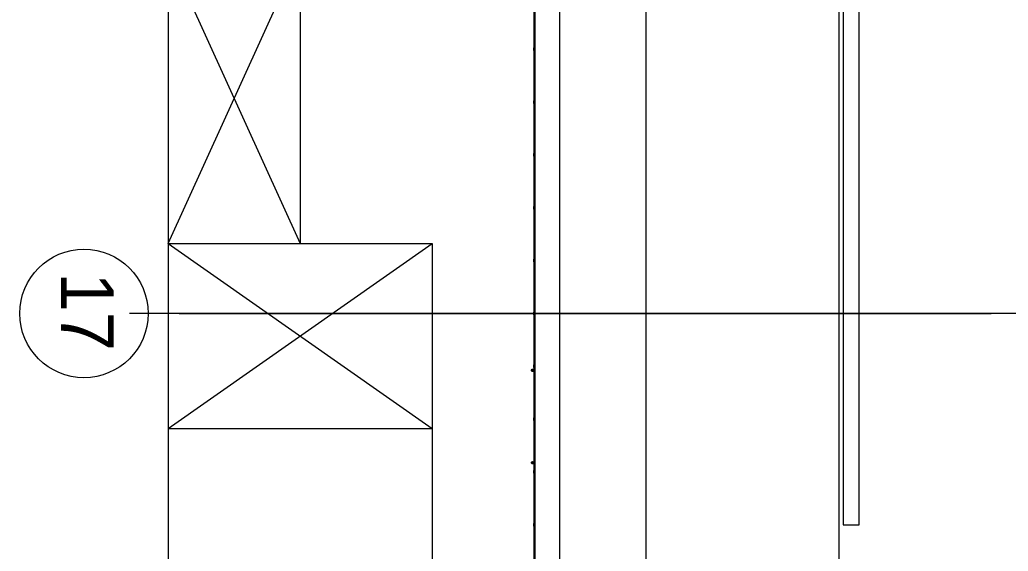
# Model space of a CAD drawing. Extents: x -264165 to -263575, y -1242333 to -1242036.
# Drawn here: x -263923.9 to -263905.18, y -1242193.38 to -1242183.32 of the extents above; entities that cross this region are included whole.
import ezdxf

# ---------------------------------------------------------------- set-up
doc = ezdxf.new("R2010")
doc.units = 0
doc.layers.add('KFA_HESCON_OSI_STAVBY', color=7, linetype='Continuous')
doc.layers.add('KFA_SITUACIA_DRS_VYTYCOVAK_SEDA', color=7, linetype='Continuous')

msp = doc.modelspace()

# ---------------------------------------------------------------- linework, layer by layer
at = {"layer": 'KFA_HESCON_OSI_STAVBY'}
for p, q in [((-263908.393, -1242080.447), (-263908.393, -1242248.737)), ((-263787.486, -1242188.882), (-263921.823, -1242188.882)), ((-263920.885, -1242188.882), (-263905.505, -1242188.882))]:
    msp.add_line(p, q, dxfattribs=at)
msp.add_circle((-263922.688, -1242188.882), 1.216, dxfattribs=at)
at = {"layer": 'KFA_SITUACIA_DRS_VYTYCOVAK_SEDA'}
for p, q in [((-263921.093, -1242087.308), (-263921.093, -1242241.458)), ((-263912.043, -1242228.625), (-263912.043, -1242100.14)), ((-263914.153, -1242132.422), (-263914.153, -1242196.342)), ((-263914.153, -1242132.422), (-263914.153, -1242196.342)), ((-263914.143, -1242196.333), (-263914.143, -1242132.433)), ((-263913.683, -1242132.892), (-263913.683, -1242195.872)), ((-263913.683, -1242132.892), (-263913.683, -1242195.872)), ((-263908.308, -1242135.882), (-263908.308, -1242192.882)), ((-263908.308, -1242135.882), (-263908.308, -1242192.882)), ((-263908.008, -1242192.882), (-263908.008, -1242135.882)), ((-263908.008, -1242192.882), (-263908.008, -1242135.882)), ((-263918.593, -1242141.207), (-263918.593, -1242187.557)), ((-263921.093, -1242182.062), (-263918.593, -1242187.557)), ((-263921.093, -1242187.557), (-263918.593, -1242182.062)), ((-263914.168, -1242182.907), (-263914.168, -1242183.857)), ((-263914.168, -1242182.907), (-263914.168, -1242183.857)), ((-263914.168, -1242183.907), (-263914.168, -1242183.857)), ((-263914.168, -1242183.907), (-263914.168, -1242183.857)), ((-263914.168, -1242183.907), (-263914.168, -1242184.857)), ((-263914.168, -1242183.907), (-263914.168, -1242184.857)), ((-263914.168, -1242184.907), (-263914.168, -1242184.857)), ((-263914.168, -1242184.907), (-263914.168, -1242184.857)), ((-263914.168, -1242184.907), (-263914.168, -1242185.857)), ((-263914.168, -1242184.907), (-263914.168, -1242185.857)), ((-263914.168, -1242185.907), (-263914.168, -1242185.857)), ((-263914.168, -1242185.907), (-263914.168, -1242185.857)), ((-263914.168, -1242185.907), (-263914.168, -1242186.857)), ((-263914.168, -1242185.907), (-263914.168, -1242186.857)), ((-263914.168, -1242186.907), (-263914.168, -1242186.857)), ((-263914.168, -1242186.907), (-263914.168, -1242186.857)), ((-263914.168, -1242186.907), (-263914.168, -1242187.857)), ((-263914.168, -1242186.907), (-263914.168, -1242187.857)), ((-263921.093, -1242187.557), (-263916.093, -1242187.557)), ((-263921.093, -1242187.557), (-263916.093, -1242191.057)), ((-263921.093, -1242191.057), (-263916.093, -1242187.557)), ((-263916.093, -1242187.557), (-263916.093, -1242241.458)), ((-263914.168, -1242187.907), (-263914.168, -1242187.857)), ((-263914.168, -1242187.907), (-263914.168, -1242187.857)), ((-263914.168, -1242187.907), (-263914.168, -1242188.857)), ((-263914.168, -1242187.907), (-263914.168, -1242188.857)), ((-263914.168, -1242188.907), (-263914.168, -1242188.857)), ((-263914.168, -1242188.907), (-263914.168, -1242188.857)), ((-263914.168, -1242188.907), (-263914.168, -1242189.857)), ((-263914.168, -1242188.907), (-263914.168, -1242189.857)), ((-263914.213, -1242189.957), (-263914.21, -1242189.947)), ((-263914.213, -1242189.957), (-263914.21, -1242189.947)), ((-263914.21, -1242189.967), (-263914.213, -1242189.957)), ((-263914.21, -1242189.967), (-263914.213, -1242189.957)), ((-263914.21, -1242189.947), (-263914.203, -1242189.939)), ((-263914.21, -1242189.947), (-263914.203, -1242189.939)), ((-263914.21, -1242189.948), (-263914.21, -1242189.947)), ((-263914.21, -1242189.948), (-263914.21, -1242189.947)), ((-263914.21, -1242189.952), (-263914.21, -1242189.948)), ((-263914.21, -1242189.952), (-263914.21, -1242189.948)), ((-263914.21, -1242189.957), (-263914.21, -1242189.952)), ((-263914.21, -1242189.957), (-263914.21, -1242189.952)), ((-263914.21, -1242189.962), (-263914.21, -1242189.957)), ((-263914.21, -1242189.962), (-263914.21, -1242189.957)), ((-263914.21, -1242189.965), (-263914.21, -1242189.962)), ((-263914.21, -1242189.965), (-263914.21, -1242189.962)), ((-263914.21, -1242189.967), (-263914.21, -1242189.965)), ((-263914.21, -1242189.967), (-263914.21, -1242189.965)), ((-263914.203, -1242189.974), (-263914.21, -1242189.967)), ((-263914.203, -1242189.974), (-263914.21, -1242189.967)), ((-263914.203, -1242189.939), (-263914.193, -1242189.937)), ((-263914.203, -1242189.939), (-263914.193, -1242189.937)), ((-263914.203, -1242189.942), (-263914.203, -1242189.939)), ((-263914.203, -1242189.942), (-263914.203, -1242189.939)), ((-263914.203, -1242189.942), (-263914.193, -1242189.939)), ((-263914.203, -1242189.942), (-263914.193, -1242189.939)), ((-263914.203, -1242189.948), (-263914.203, -1242189.942)), ((-263914.203, -1242189.948), (-263914.203, -1242189.942)), ((-263914.203, -1242189.948), (-263914.193, -1242189.947)), ((-263914.203, -1242189.948), (-263914.193, -1242189.947)), ((-263914.203, -1242189.957), (-263914.203, -1242189.948)), ((-263914.203, -1242189.957), (-263914.203, -1242189.948)), ((-263914.203, -1242189.965), (-263914.203, -1242189.957)), ((-263914.203, -1242189.965), (-263914.203, -1242189.957)), ((-263914.203, -1242189.957), (-263914.193, -1242189.957)), ((-263914.203, -1242189.957), (-263914.193, -1242189.957)), ((-263914.203, -1242189.965), (-263914.193, -1242189.967)), ((-263914.203, -1242189.965), (-263914.193, -1242189.967)), ((-263914.203, -1242189.972), (-263914.203, -1242189.965)), ((-263914.203, -1242189.972), (-263914.203, -1242189.965)), ((-263914.203, -1242189.974), (-263914.203, -1242189.972)), ((-263914.203, -1242189.974), (-263914.203, -1242189.972)), ((-263914.203, -1242189.972), (-263914.193, -1242189.974)), ((-263914.203, -1242189.972), (-263914.193, -1242189.974)), ((-263914.193, -1242189.977), (-263914.203, -1242189.974)), ((-263914.193, -1242189.977), (-263914.203, -1242189.974)), ((-263914.193, -1242189.937), (-263914.183, -1242189.939)), ((-263914.193, -1242189.937), (-263914.183, -1242189.939)), ((-263914.193, -1242189.937), (-263914.193, -1242189.939)), ((-263914.193, -1242189.937), (-263914.193, -1242189.939)), ((-263914.193, -1242189.939), (-263914.183, -1242189.942)), ((-263914.193, -1242189.939), (-263914.183, -1242189.942)), ((-263914.193, -1242189.939), (-263914.193, -1242189.947)), ((-263914.193, -1242189.939), (-263914.193, -1242189.947)), ((-263914.193, -1242189.947), (-263914.193, -1242189.957)), ((-263914.193, -1242189.947), (-263914.193, -1242189.957)), ((-263914.193, -1242189.947), (-263914.183, -1242189.948)), ((-263914.193, -1242189.947), (-263914.183, -1242189.948)), ((-263914.193, -1242189.957), (-263914.193, -1242189.967)), ((-263914.193, -1242189.957), (-263914.193, -1242189.967)), ((-263914.193, -1242189.957), (-263914.183, -1242189.957)), ((-263914.193, -1242189.957), (-263914.183, -1242189.957)), ((-263914.193, -1242189.967), (-263914.183, -1242189.965)), ((-263914.193, -1242189.967), (-263914.183, -1242189.965)), ((-263914.193, -1242189.967), (-263914.193, -1242189.974)), ((-263914.193, -1242189.967), (-263914.193, -1242189.974)), ((-263914.193, -1242189.974), (-263914.183, -1242189.972)), ((-263914.193, -1242189.974), (-263914.183, -1242189.972)), ((-263914.193, -1242189.974), (-263914.193, -1242189.977)), ((-263914.193, -1242189.974), (-263914.193, -1242189.977)), ((-263914.183, -1242189.974), (-263914.193, -1242189.977)), ((-263914.183, -1242189.974), (-263914.193, -1242189.977)), ((-263914.183, -1242189.939), (-263914.176, -1242189.947)), ((-263914.183, -1242189.939), (-263914.176, -1242189.947)), ((-263914.183, -1242189.939), (-263914.183, -1242189.942)), ((-263914.183, -1242189.939), (-263914.183, -1242189.942)), ((-263914.183, -1242189.942), (-263914.183, -1242189.948)), ((-263914.183, -1242189.942), (-263914.183, -1242189.948)), ((-263914.183, -1242189.948), (-263914.183, -1242189.957)), ((-263914.183, -1242189.948), (-263914.183, -1242189.957)), ((-263914.183, -1242189.957), (-263914.183, -1242189.965)), ((-263914.183, -1242189.957), (-263914.183, -1242189.965)), ((-263914.183, -1242189.965), (-263914.183, -1242189.972)), ((-263914.183, -1242189.965), (-263914.183, -1242189.972)), ((-263914.176, -1242189.967), (-263914.183, -1242189.974)), ((-263914.176, -1242189.967), (-263914.183, -1242189.974)), ((-263914.183, -1242189.972), (-263914.183, -1242189.974)), ((-263914.183, -1242189.972), (-263914.183, -1242189.974)), ((-263914.176, -1242189.947), (-263914.168, -1242189.947)), ((-263914.176, -1242189.947), (-263914.168, -1242189.947)), ((-263914.176, -1242189.947), (-263914.176, -1242189.948)), ((-263914.176, -1242189.947), (-263914.176, -1242189.948)), ((-263914.176, -1242189.948), (-263914.168, -1242189.948)), ((-263914.176, -1242189.948), (-263914.168, -1242189.948)), ((-263914.176, -1242189.948), (-263914.176, -1242189.952)), ((-263914.176, -1242189.948), (-263914.176, -1242189.952)), ((-263914.176, -1242189.952), (-263914.168, -1242189.952)), ((-263914.176, -1242189.952), (-263914.168, -1242189.952)), ((-263914.176, -1242189.952), (-263914.176, -1242189.957)), ((-263914.176, -1242189.952), (-263914.176, -1242189.957)), ((-263914.176, -1242189.957), (-263914.168, -1242189.957)), ((-263914.176, -1242189.957), (-263914.168, -1242189.957)), ((-263914.176, -1242189.957), (-263914.176, -1242189.962)), ((-263914.176, -1242189.957), (-263914.176, -1242189.962)), ((-263914.176, -1242189.962), (-263914.168, -1242189.962)), ((-263914.176, -1242189.962), (-263914.168, -1242189.962)), ((-263914.176, -1242189.962), (-263914.176, -1242189.965)), ((-263914.176, -1242189.962), (-263914.176, -1242189.965)), ((-263914.176, -1242189.965), (-263914.168, -1242189.965)), ((-263914.176, -1242189.965), (-263914.168, -1242189.965)), ((-263914.176, -1242189.965), (-263914.176, -1242189.967)), ((-263914.176, -1242189.965), (-263914.176, -1242189.967)), ((-263914.176, -1242189.967), (-263914.168, -1242189.967)), ((-263914.176, -1242189.967), (-263914.168, -1242189.967)), ((-263914.168, -1242189.907), (-263914.168, -1242189.857)), ((-263914.168, -1242189.907), (-263914.168, -1242189.857)), ((-263914.168, -1242189.907), (-263914.168, -1242190.857)), ((-263914.168, -1242189.907), (-263914.168, -1242190.857)), ((-263914.168, -1242190.907), (-263914.168, -1242190.857)), ((-263914.168, -1242190.907), (-263914.168, -1242190.857)), ((-263914.168, -1242190.907), (-263914.168, -1242191.857)), ((-263914.168, -1242190.907), (-263914.168, -1242191.857)), ((-263921.093, -1242191.057), (-263916.093, -1242191.057)), ((-263914.213, -1242191.707), (-263914.21, -1242191.697)), ((-263914.213, -1242191.707), (-263914.21, -1242191.697)), ((-263914.21, -1242191.717), (-263914.213, -1242191.707)), ((-263914.21, -1242191.717), (-263914.213, -1242191.707)), ((-263914.21, -1242191.697), (-263914.203, -1242191.689)), ((-263914.21, -1242191.697), (-263914.203, -1242191.689)), ((-263914.21, -1242191.698), (-263914.21, -1242191.697)), ((-263914.21, -1242191.698), (-263914.21, -1242191.697)), ((-263914.21, -1242191.702), (-263914.21, -1242191.698)), ((-263914.21, -1242191.702), (-263914.21, -1242191.698)), ((-263914.21, -1242191.707), (-263914.21, -1242191.702)), ((-263914.21, -1242191.707), (-263914.21, -1242191.702)), ((-263914.21, -1242191.712), (-263914.21, -1242191.707)), ((-263914.21, -1242191.712), (-263914.21, -1242191.707)), ((-263914.21, -1242191.715), (-263914.21, -1242191.712)), ((-263914.21, -1242191.715), (-263914.21, -1242191.712)), ((-263914.21, -1242191.717), (-263914.21, -1242191.715)), ((-263914.21, -1242191.717), (-263914.21, -1242191.715)), ((-263914.203, -1242191.724), (-263914.21, -1242191.717)), ((-263914.203, -1242191.724), (-263914.21, -1242191.717)), ((-263914.203, -1242191.689), (-263914.193, -1242191.687)), ((-263914.203, -1242191.689), (-263914.193, -1242191.687)), ((-263914.203, -1242191.692), (-263914.203, -1242191.689)), ((-263914.203, -1242191.692), (-263914.203, -1242191.689)), ((-263914.203, -1242191.692), (-263914.193, -1242191.689)), ((-263914.203, -1242191.692), (-263914.193, -1242191.689)), ((-263914.203, -1242191.698), (-263914.203, -1242191.692)), ((-263914.203, -1242191.698), (-263914.203, -1242191.692)), ((-263914.203, -1242191.698), (-263914.193, -1242191.697)), ((-263914.203, -1242191.698), (-263914.193, -1242191.697)), ((-263914.203, -1242191.707), (-263914.203, -1242191.698)), ((-263914.203, -1242191.707), (-263914.203, -1242191.698)), ((-263914.203, -1242191.715), (-263914.203, -1242191.707)), ((-263914.203, -1242191.715), (-263914.203, -1242191.707)), ((-263914.203, -1242191.707), (-263914.193, -1242191.707)), ((-263914.203, -1242191.707), (-263914.193, -1242191.707)), ((-263914.203, -1242191.715), (-263914.193, -1242191.717)), ((-263914.203, -1242191.715), (-263914.193, -1242191.717)), ((-263914.203, -1242191.722), (-263914.203, -1242191.715)), ((-263914.203, -1242191.722), (-263914.203, -1242191.715)), ((-263914.203, -1242191.724), (-263914.203, -1242191.722)), ((-263914.203, -1242191.724), (-263914.203, -1242191.722)), ((-263914.203, -1242191.722), (-263914.193, -1242191.724)), ((-263914.203, -1242191.722), (-263914.193, -1242191.724)), ((-263914.193, -1242191.727), (-263914.203, -1242191.724)), ((-263914.193, -1242191.727), (-263914.203, -1242191.724)), ((-263914.193, -1242191.687), (-263914.183, -1242191.689)), ((-263914.193, -1242191.687), (-263914.183, -1242191.689)), ((-263914.193, -1242191.687), (-263914.193, -1242191.689)), ((-263914.193, -1242191.687), (-263914.193, -1242191.689)), ((-263914.193, -1242191.689), (-263914.183, -1242191.692)), ((-263914.193, -1242191.689), (-263914.183, -1242191.692)), ((-263914.193, -1242191.689), (-263914.193, -1242191.697)), ((-263914.193, -1242191.689), (-263914.193, -1242191.697)), ((-263914.193, -1242191.697), (-263914.193, -1242191.707)), ((-263914.193, -1242191.697), (-263914.193, -1242191.707)), ((-263914.193, -1242191.697), (-263914.183, -1242191.698)), ((-263914.193, -1242191.697), (-263914.183, -1242191.698)), ((-263914.193, -1242191.707), (-263914.193, -1242191.717)), ((-263914.193, -1242191.707), (-263914.193, -1242191.717)), ((-263914.193, -1242191.707), (-263914.183, -1242191.707)), ((-263914.193, -1242191.707), (-263914.183, -1242191.707)), ((-263914.193, -1242191.717), (-263914.183, -1242191.715)), ((-263914.193, -1242191.717), (-263914.183, -1242191.715)), ((-263914.193, -1242191.717), (-263914.193, -1242191.724)), ((-263914.193, -1242191.717), (-263914.193, -1242191.724)), ((-263914.193, -1242191.724), (-263914.183, -1242191.722)), ((-263914.193, -1242191.724), (-263914.183, -1242191.722)), ((-263914.193, -1242191.724), (-263914.193, -1242191.727)), ((-263914.193, -1242191.724), (-263914.193, -1242191.727)), ((-263914.183, -1242191.724), (-263914.193, -1242191.727)), ((-263914.183, -1242191.724), (-263914.193, -1242191.727)), ((-263914.183, -1242191.689), (-263914.176, -1242191.697)), ((-263914.183, -1242191.689), (-263914.176, -1242191.697)), ((-263914.183, -1242191.689), (-263914.183, -1242191.692)), ((-263914.183, -1242191.689), (-263914.183, -1242191.692)), ((-263914.183, -1242191.692), (-263914.183, -1242191.698)), ((-263914.183, -1242191.692), (-263914.183, -1242191.698)), ((-263914.183, -1242191.698), (-263914.183, -1242191.707)), ((-263914.183, -1242191.698), (-263914.183, -1242191.707)), ((-263914.183, -1242191.707), (-263914.183, -1242191.715)), ((-263914.183, -1242191.707), (-263914.183, -1242191.715)), ((-263914.183, -1242191.715), (-263914.183, -1242191.722)), ((-263914.183, -1242191.715), (-263914.183, -1242191.722)), ((-263914.176, -1242191.717), (-263914.183, -1242191.724)), ((-263914.176, -1242191.717), (-263914.183, -1242191.724)), ((-263914.183, -1242191.722), (-263914.183, -1242191.724)), ((-263914.183, -1242191.722), (-263914.183, -1242191.724)), ((-263914.176, -1242191.697), (-263914.168, -1242191.697)), ((-263914.176, -1242191.697), (-263914.168, -1242191.697)), ((-263914.176, -1242191.697), (-263914.176, -1242191.698)), ((-263914.176, -1242191.697), (-263914.176, -1242191.698)), ((-263914.176, -1242191.698), (-263914.168, -1242191.698)), ((-263914.176, -1242191.698), (-263914.168, -1242191.698)), ((-263914.176, -1242191.698), (-263914.176, -1242191.702)), ((-263914.176, -1242191.698), (-263914.176, -1242191.702)), ((-263914.176, -1242191.702), (-263914.168, -1242191.702)), ((-263914.176, -1242191.702), (-263914.168, -1242191.702)), ((-263914.176, -1242191.702), (-263914.176, -1242191.707)), ((-263914.176, -1242191.702), (-263914.176, -1242191.707)), ((-263914.176, -1242191.707), (-263914.168, -1242191.707)), ((-263914.176, -1242191.707), (-263914.168, -1242191.707)), ((-263914.176, -1242191.707), (-263914.176, -1242191.712)), ((-263914.176, -1242191.707), (-263914.176, -1242191.712)), ((-263914.176, -1242191.712), (-263914.168, -1242191.712)), ((-263914.176, -1242191.712), (-263914.168, -1242191.712)), ((-263914.176, -1242191.712), (-263914.176, -1242191.715)), ((-263914.176, -1242191.712), (-263914.176, -1242191.715)), ((-263914.176, -1242191.715), (-263914.168, -1242191.715)), ((-263914.176, -1242191.715), (-263914.168, -1242191.715)), ((-263914.176, -1242191.715), (-263914.176, -1242191.717)), ((-263914.176, -1242191.715), (-263914.176, -1242191.717)), ((-263914.176, -1242191.717), (-263914.168, -1242191.717)), ((-263914.176, -1242191.717), (-263914.168, -1242191.717)), ((-263914.168, -1242191.907), (-263914.168, -1242191.857)), ((-263914.168, -1242191.907), (-263914.168, -1242191.857)), ((-263914.168, -1242191.907), (-263914.168, -1242192.857)), ((-263914.168, -1242191.907), (-263914.168, -1242192.857)), ((-263914.168, -1242192.907), (-263914.168, -1242192.857)), ((-263914.168, -1242192.907), (-263914.168, -1242192.857)), ((-263914.168, -1242192.907), (-263914.168, -1242193.857)), ((-263914.168, -1242192.907), (-263914.168, -1242193.857)), ((-263908.308, -1242192.882), (-263908.008, -1242192.882)), ((-263908.308, -1242192.882), (-263908.008, -1242192.882))]:
    msp.add_line(p, q, dxfattribs=at)

# ---------------------------------------------------------------- texts
at = {"layer": 'KFA_HESCON_OSI_STAVBY'}
msp.add_text('17', height=1, rotation=270, dxfattribs=at).set_placement((-263923.123, -1242188.105))

doc.saveas('drawing.dxf')
